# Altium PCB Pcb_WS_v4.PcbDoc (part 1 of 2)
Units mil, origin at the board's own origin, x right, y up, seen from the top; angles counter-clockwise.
Board outline 3890 x 3890 mil, 2 copper layers (Top Layer, Bottom Layer); 77 components, 63 nets, 250 pads, 399 vias.
Unrouted connection lines stored in the file: 3.
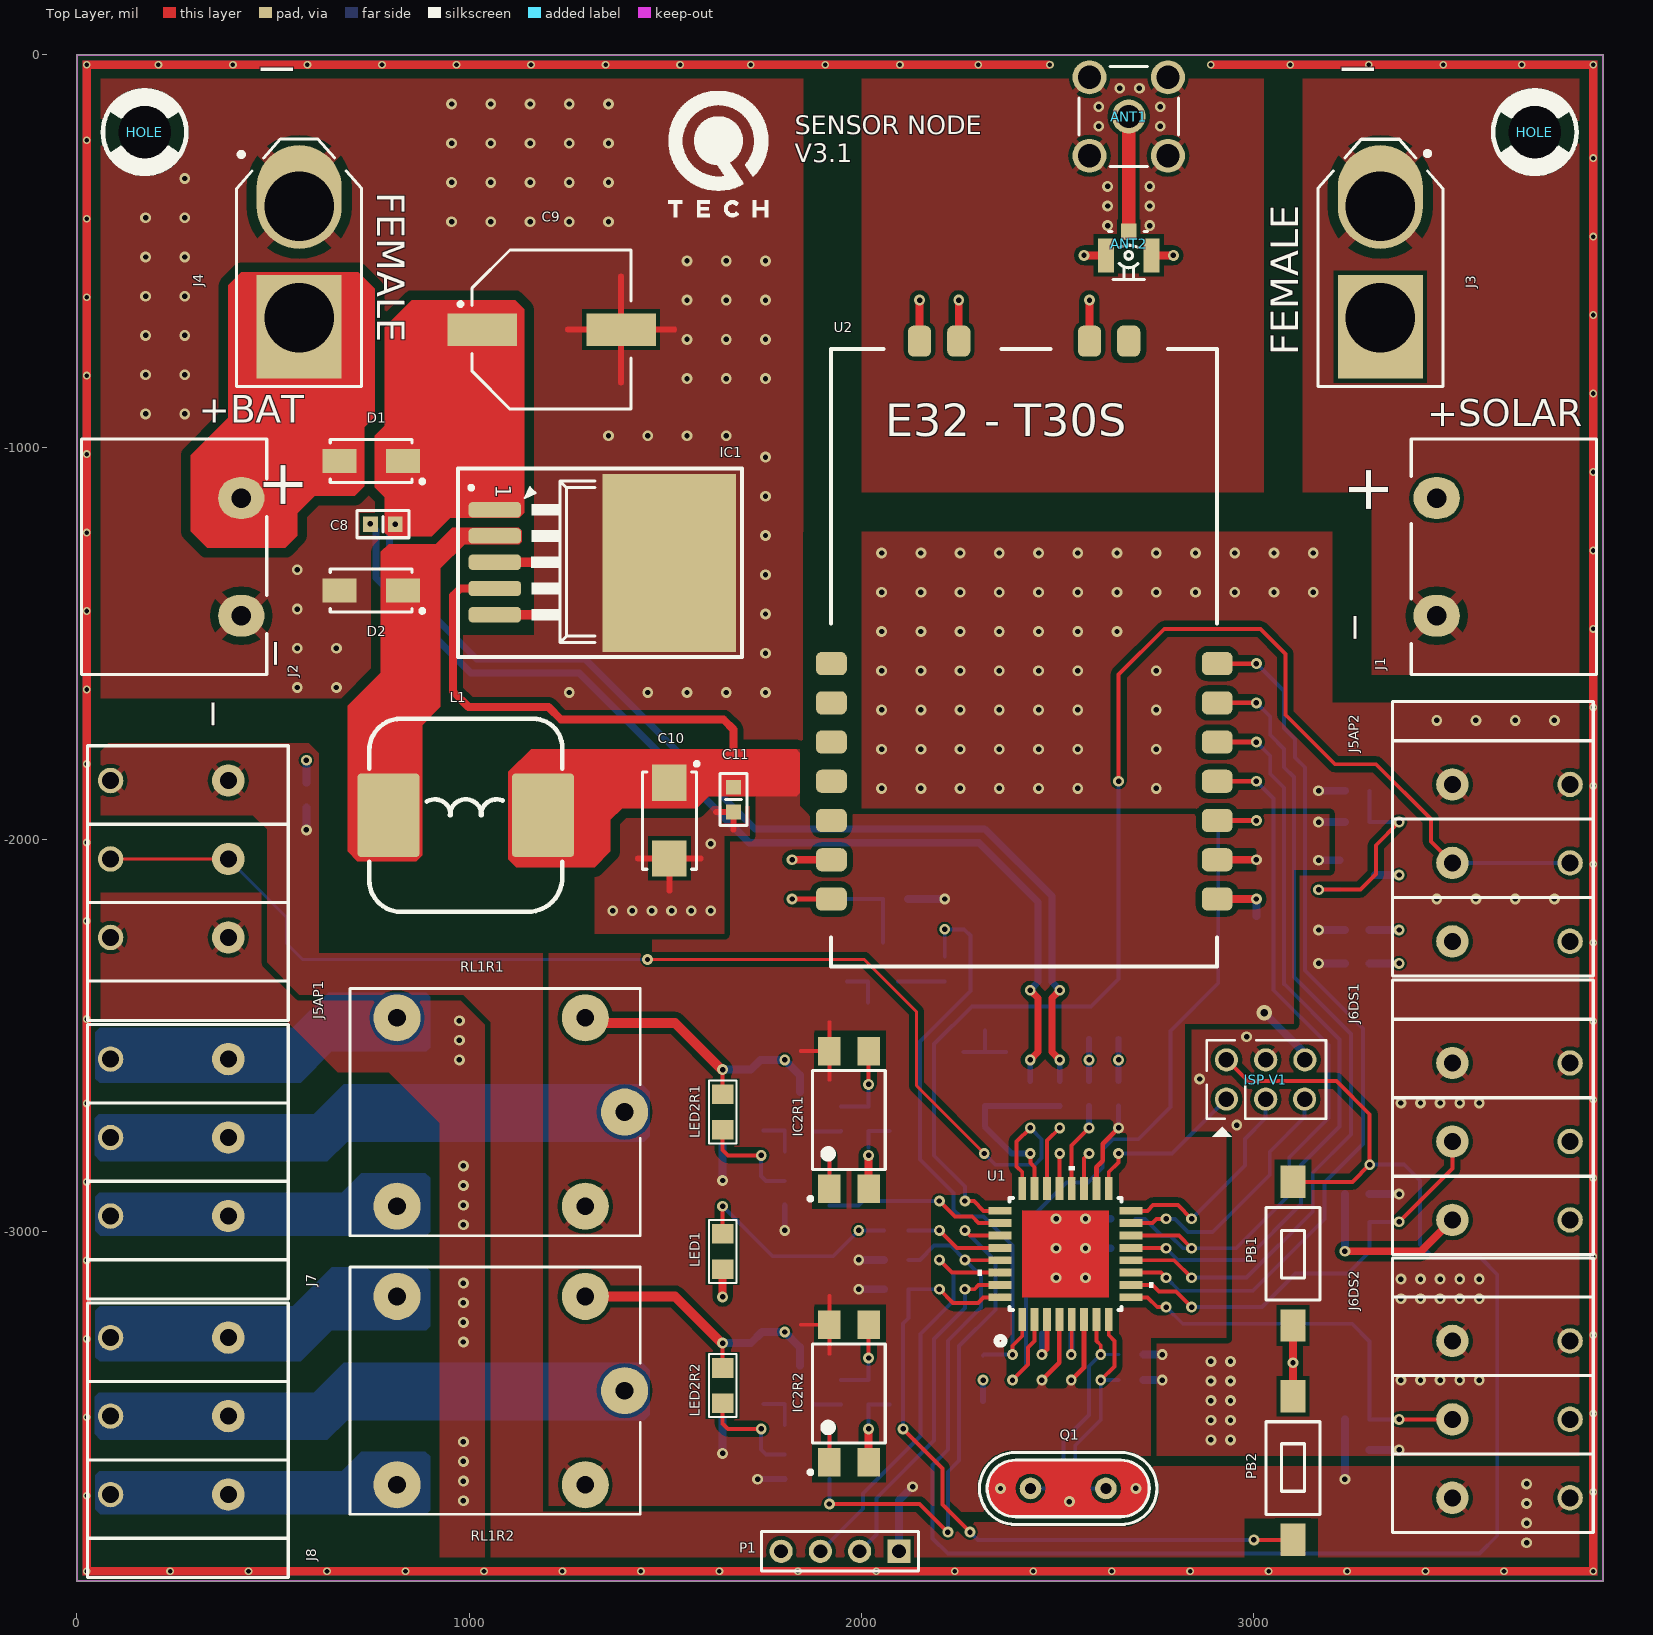
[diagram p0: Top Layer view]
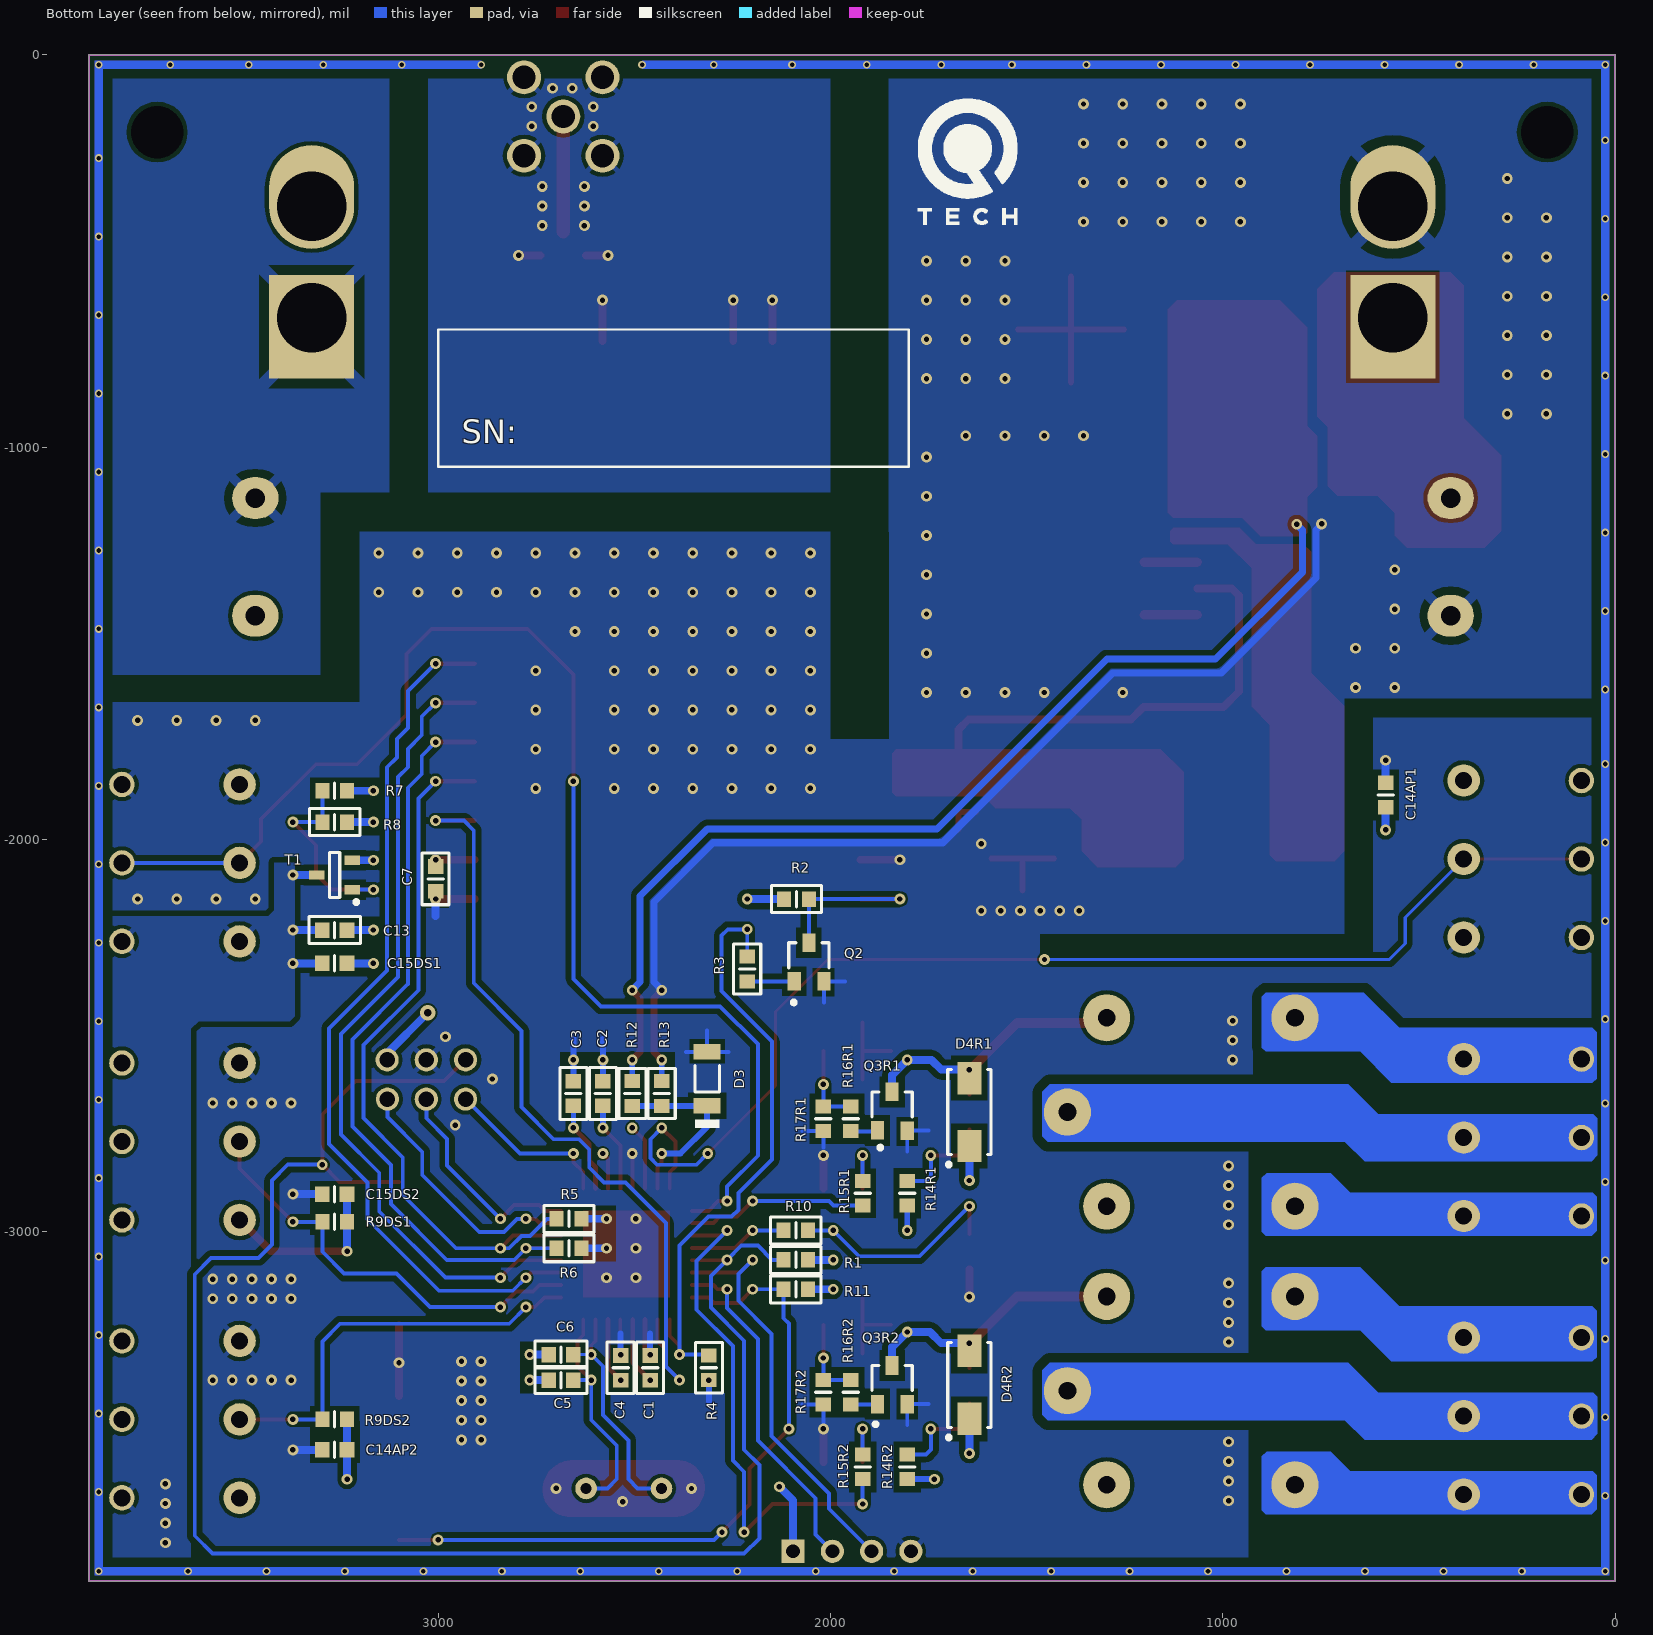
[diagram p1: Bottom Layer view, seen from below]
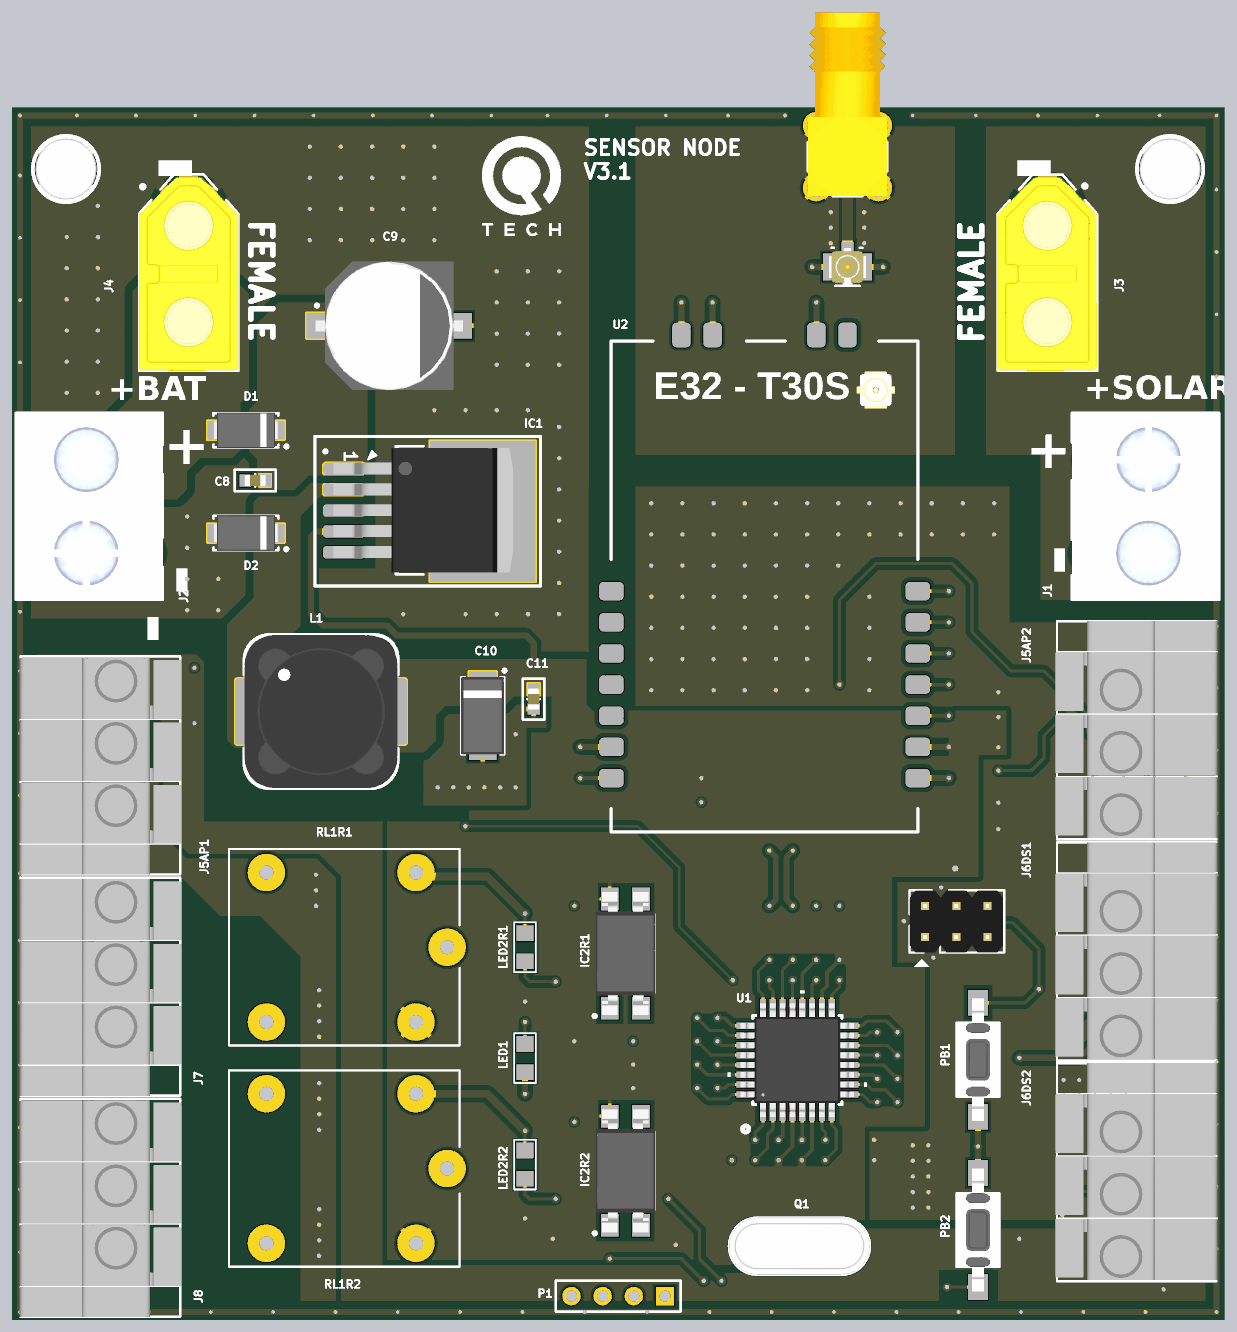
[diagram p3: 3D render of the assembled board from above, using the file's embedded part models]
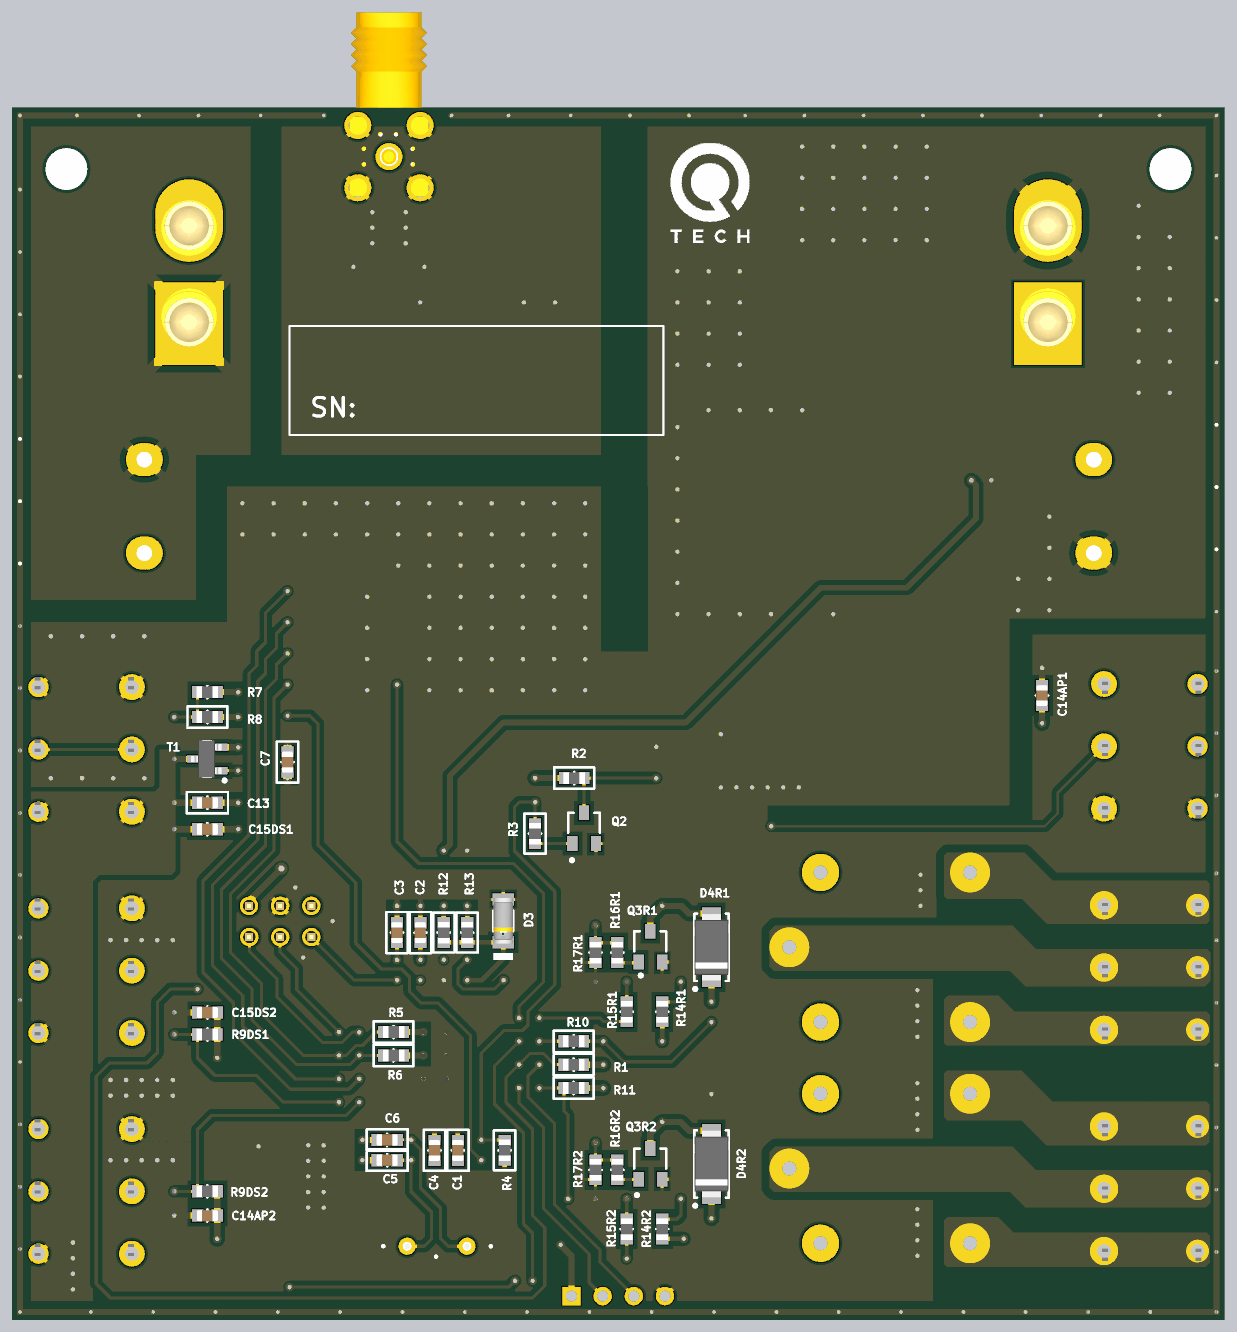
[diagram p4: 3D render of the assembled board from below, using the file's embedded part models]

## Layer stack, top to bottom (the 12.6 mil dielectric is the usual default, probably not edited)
Top Solder: solder mask 0.4, Solder Resist, Dk 3.5
Top Layer: signal copper 1.4
Dielectric 1: dielectric 12.6, FR-4, Dk 4.8
Bottom Layer: signal copper 1.4
Bottom Solder: solder mask 0.4, Solder Resist, Dk 3.5

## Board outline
0,-3890 0,0 3890,0 3890,-3890

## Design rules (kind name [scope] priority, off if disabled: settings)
Clearance ANT [InNet('ANT_M1') vs InNet('GND_ANT')] p1: gap=10 ignorepadtopadclearanceinfootprint=FALSE
Clearance Keep_Out [OnLayer('Keep-Out Layer')] p2: gap=5 ignorepadtopadclearanceinfootprint=FALSE
Clearance [All] p3: gap=10 ignorepadtopadclearanceinfootprint=FALSE except(5: Via-Poly Via-Region; 15: Track-Poly Track-Region SMDPad-Poly SMDPad-Region Poly-Poly; 25: Poly-Region)
ComponentClearance KF-conn_Clearance [InComponentClass('KF_conn') vs InComponentClass('KF_conn')] p1: gap=5 collisioncheckmode=3 verticalgap=0 showdistances=FALSE
ComponentClearance HS_Comp_Clearance [InComponentClass('HS_Comp') vs IsComponent] p2: gap=165 collisioncheckmode=3 verticalgap=0 showdistances=FALSE
ComponentClearance IC_Comp_Clearance [InComponentClass('IC_Comp') vs IsComponent] p3: gap=150 collisioncheckmode=3 verticalgap=0 showdistances=FALSE
ComponentClearance conn-th_Clearance [InComponentClass('conn-th') vs IsComponent and not InComponentClass('conn-th')] p4: gap=150 collisioncheckmode=3 verticalgap=0 showdistances=FALSE
ComponentClearance chip-ge_Clearance [InComponentClass('chip-ge') vs InAnyComponent] p5: gap=75 collisioncheckmode=3 verticalgap=0 showdistances=FALSE
ComponentClearance chip-0603_Clearance [InComponentClass('chip-0603') vs IsComponent] p6: gap=25 collisioncheckmode=3 verticalgap=0 showdistances=FALSE
HoleSize [All] p1: absolutevalues=TRUE maxlimit=100 minlimit=11.81 maxpercent=80.000 minpercent=20.000
HoleToHoleClearance [All] p1: gap=20 allowstackedmicrovias=TRUE
MinimumSolderMaskSliver MinimumForIC [HasFootprint('32A_ATM-M') vs HasFootprint('32A_ATM-M')] p1: minsoldermaskwidth=3
MinimumSolderMaskSliver [All] p2: minsoldermaskwidth=5
NetAntennae [All] p1 off: netantennaetolerance=0
PolygonConnect [All] p1: thpad.connectstyle=Relief thpad.reliefconductorwidth=13.78 thpad.reliefentries=4 thpad.polygonreliefangle="45 Angle" thpad.airgapwidth=10 smdpad.connectstyle=NoConnect smdpad.reliefconductorwidth=11.81 smdpad.reliefentries=4 smdpad.polygonreliefangle="45 Angle" smdpad.airgapwidth=10 via.connectstyle=Direct via.reliefconductorwidth=10 via.reliefentries=4 via.polygonreliefangle="90 Angle" via.airgapwidth=10
RoutingVias [All] p1: holewidth=13.78 width=27.56 viastyle="Through Hole" minholewidth=11.81 minwidth=23.62 maxholewidth=19.68 maxwidth=39.37
SilkToSilkClearance [All] p1: silktosilkclearance=3
SilkToSolderMaskClearance [IsPad] p1: minsilkscreentomaskgap=5 clearancetoexposedcopper=TRUE
SolderMaskExpansion [All] p1: expansion=4 istentingtop=FALSE
Width [All] p1: maxlimit=196.85 minlimit=8 preferedwidth=10
23 further rules are at their usual default settings.

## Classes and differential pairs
polygon class "New Class": AutoNaming "Top Layer-No Net"
component class KF_conn: J5AP1 J5AP2 J6DS1 J6DS2 J7 J8
component class HS_Comp: ANT1 ANT2 Q1
component class IC_Comp: IC1 IC2R1 IC2R2 L1 U1 U2
component class chip-ge: C9 C10 D1 D2 D4R1 D4R2
component class conn-th: "ISP V1" J1 J2 J3 J4 J5AP1 J5AP2 J6DS1 J6DS2 J7 J8 P1 PB1 PB2 RL1R1 RL1R2
component class chip-0603: C1 C2 C3 C4 C5 C6 C7 C8 C11 C13 C14AP1 C14AP2 C15DS1 C15DS2 D3 LED1 LED2R1 LED2R2 Q2 Q3R1 Q3R2 R1 R2 R3 R4 R5 R6 R7 R8 R9DS1 R9DS2 R10 R11 R12 R13 R14R1 R14R2 R15R1 R15R2 R16R1 R16R2 R17R1 R17R2 T1
channel class Sensor_DS18b20_1Wire: DS1 DS2
channel class Sensor_AirPressure_1Wire: AP1 AP2
channel class Relay: R1 R2
component class Top_Level: D3 HOLE J7 J8 LED1 P1 PB2 R10 R11 R12 R13
component class R2: D4R2 IC2R2 LED2R2 Q3R2 R14R2 R15R2 R16R2 R17R2 RL1R2
component class R1: D4R1 IC2R1 LED2R1 Q3R1 R14R1 R15R1 R16R1 R17R1 RL1R1
component class Main: C1 C2 C3 C4 C5 C6 "ISP V1" PB1 Q1 R1 U1
component class Lora: ANT1 ANT2 C7 Q2 R2 R3 R4 R5 R6 U2
component class DS2: C15DS2 J6DS2 R9DS2
component class DS1: C15DS1 J6DS1 R9DS1
component class AP2: C14AP2 J5AP2
component class AP1: C14AP1 J5AP1
component class PWR: C8 C9 C10 C11 C13 D1 D2 IC1 J1 J2 J3 J4 L1 R7 R8 T1

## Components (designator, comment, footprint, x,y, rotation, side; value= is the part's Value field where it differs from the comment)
ANT1 "Coax_1Female_1Shield" "HUBER-SUHNER_85 SMA-50-0-101/111 NE" 2680.84,-157 r90 top
ANT2 "U.FL" HIROSE_U.FL-R-SMT-1(10) 2680.84,-511 r180 top
C1 "100nF" CAPC1608X87N 2459.61,-3346.32 r90 bottom
C2 "100nF" CAPC1608X87N 2580,-2647.18 r270 bottom
C3 "100nF" CAPC1608X87N 2655,-2647.18 r90 bottom
C4 "100nF" CAPC1608X87N 2534.61,-3346.32 r90 bottom
C5 "100nF" CAPC1608X87N 2686.8,-3377.82 r0 bottom value=22pF
C6 "100nF" CAPC1608X87N 2686.8,-3312.82 r0 bottom value=22pF
C7 "100nF" CAPC1608X87N 3006.43,-2100 r270 bottom
C8 "100nF" CAPC1608X87N 780,-1196.11 r180 top
C9 "470uF" CAPAE1030X1020N 1210,-700 r0 top
C10 "100uF" CAPMP6032X280N 1510,-1951.51 r270 top
C11 "100nF" CAPC1608X87N 1673.55,-1898 r270 top
C13 "100nF" CAPC1608X87N 3263.5,-2230.54 r180 bottom
C14AP1 "100nF" CAPC1608X87N 585,-1886.5 r270 bottom (schematic designator C14)
C14AP2 "100nF" CAPC1608X87N 3263.5,-3555.54 r180 bottom (schematic designator C14)
C15DS1 "100nF" CAPC1608X87N 3263.5,-2315.54 r0 bottom (schematic designator C15)
C15DS2 "100nF" CAPC1608X87N 3263.5,-2903.69 r180 bottom (schematic designator C15)
D1 "SS16" DIOM5127X229N 750,-1035 r180 top
D2 "SS16" DIOM5127X229N 750,-1365 r180 top
D3 "BZV55-B5V1" DIOMELF3515N 2314.07,-2609.78 r90 bottom
D4R1 "BZG03C220" DIOM5326X230N 1645.86,-2694.46 r90 bottom (schematic designator D4)
D4R2 "BZG03C220" DIOM5326X230N 1645.86,-3390 r90 bottom (schematic designator D4)
HOLE "HOLE" "HOLE M3" 3716.02,-196.86 r0 top
HOLE "HOLE" "HOLE M3" 172.71,-196.86 r0 top
IC1 "LM2596" TO263-5 1065.04,-1159.18 r270 top
IC2R1 "SFH6156-4" SOIC254P977X406-4N 1967.86,-2714.46 r90 top (schematic designator IC2)
IC2R2 "SFH6156-4" SOIC254P977X406-4N 1967.86,-3411.74 r90 top (schematic designator IC2)
"ISP V1" "Connector 3x2" JP3x2 3030,-2611.61 r0 top
J1 "CON KF7.62-2P" "CON KF7.62-2P" 3465.86,-1279.46 r270 top locked
J2 "CON KF7.62-2P" "CON KF7.62-2P" 418.93,-1279.46 r90 top locked
J3 "XT60-FM" XT60-FM 3322.31,-527.57 r270 top locked
J4 "XT60-FM" XT60-FM 566.41,-527.57 r270 top locked
J5AP1 "KF142V-3P" "CON KF142V-3P-5.08" 85.86,-1849.46 r270 top (schematic designator J5)
J5AP2 "KF142V-3P" "CON KF142V-3P-5.08" 3805.86,-2259.46 r90 top (schematic designator J5)
J6DS1 "KF142V-3P" "CON KF142V-3P-5.08" 3805.86,-2969.46 r90 top (schematic designator J6)
J6DS2 "KF142V-3P" "CON KF142V-3P-5.08" 3805.86,-3677.74 r90 top (schematic designator J6)
J7 "KF142V-3P" "CON KF142V-3P-5.08" 85.86,-2559.46 r270 top
J8 "KF142V-3P" "CON KF142V-3P-5.08" 85.86,-3269.46 r270 top
L1 "33uH" L_SMD 794.25,-1938 r90 top
LED1 "LED" L-0805 1645.86,-3050 r270 top value="LED 3 ly Single Colour"
LED2R1 "LED" L-0805 1645.86,-2694.46 r90 top value="LED 3 ly Single Colour" (schematic designator LED2)
LED2R2 "LED" L-0805 1645.86,-3391.74 r90 top value="LED 3 ly Single Colour" (schematic designator LED2)
P1 "Header 4" HDR1X4 2095,-3814 r180 top
PB1 "Push Button" PB_TYCO_FSMSM 3099.53,-3055.38 r270 top
PB2 "Push Button" PB_TYCO_FSMSM 3099.53,-3601.93 r90 top
Q1 "20MHz" XTAL_HC-49/U 2526.55,-3653.88 r0 top
Q2 "C1815" SOT23-3 2055.2,-2312.2 r180 bottom
Q3R1 "C1815" SOT23-3 1842.86,-2692.41 r180 bottom (schematic designator Q3)
Q3R2 "C1815" SOT23-3 1842.86,-3389.69 r180 bottom (schematic designator Q3)
R1 "10k" RESC1608X55N 2088.21,-3071.21 r0 bottom
R2 "10k" RESC1608X55N 2086.5,-2151.51 r0 bottom value=4k7
R3 "10k" RESC1608X55N 2212.06,-2329.71 r270 bottom value=1k
R4 "10k" RESC1608X55N 2309.61,-3346.32 r90 bottom value=1k
R5 "4k7" RESC1608X55N 2666.17,-2966.61 r180 bottom value=10k
R6 "4k7" RESC1608X55N 2666.17,-3041.61 r180 bottom value=10k
R7 "1k" RESC1608X55N 3263.5,-1875.54 r0 bottom
R8 "10k" RESC1608X55N 3263.5,-1955.54 r0 bottom
R9DS1 "4k7" RESC1608X55N 3263.5,-2974.23 r180 bottom (schematic designator R9)
R9DS2 "4k7" RESC1608X55N 3263.5,-3477.74 r180 bottom (schematic designator R9)
R10 "10k" RESC1608X55N 2088.21,-2996.21 r180 bottom value=200
R11 "10k" RESC1608X55N 2088.21,-3146.21 r0 bottom
R12 "10k" RESC1608X55N 2505,-2647.18 r270 bottom value=2M
R13 "10k" RESC1608X55N 2430,-2647.18 r90 bottom value=1M
R14R1 "1k" RESC1608X55N 1804.06,-2901.48 r90 bottom value=200 (schematic designator R14)
R14R2 "1k" RESC1608X55N 1804.06,-3598.76 r90 bottom value=200 (schematic designator R14)
R15R1 "1k" RESC1608X55N 1917.86,-2901.48 r90 bottom (schematic designator R15)
R15R2 "1k" RESC1608X55N 1917.86,-3598.76 r90 bottom (schematic designator R15)
R16R1 "1k" RESC1608X55N 1947.86,-2711.48 r270 bottom value=200 (schematic designator R16)
R16R2 "1k" RESC1608X55N 1947.86,-3408.76 r270 bottom value=200 (schematic designator R16)
R17R1 "10k" RESC1608X55N 2017.86,-2711.48 r90 bottom (schematic designator R17)
R17R2 "10k" RESC1608X55N 2017.86,-3408.76 r90 bottom (schematic designator R17)
RL1R1 "Relay 10A/12V" RL_SPDT_10A 1395.86,-2694.46 r180 top value="Relay SPDT, 10A, 12V" (schematic designator RL1)
RL1R2 "Relay 10A/12V" RL_SPDT_10A 1395.86,-3404.46 r180 top value="Relay SPDT, 10A, 12V" (schematic designator RL1)
T1 "BSH203" SOT95P230X110-3N 3263.5,-2090.26 r0 bottom
U1 "ATmega328-AU" 32A_ATM-M 2519.8,-3056.41 r90 top
U2 "E32-T30S" E32-T30S 2906.43,-749.15 r180 top

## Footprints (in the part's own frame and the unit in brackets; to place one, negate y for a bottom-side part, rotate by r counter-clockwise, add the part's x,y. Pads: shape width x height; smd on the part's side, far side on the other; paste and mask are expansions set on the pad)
32A_ATM-M [mil]
  rect 58x20 smd: 1(-167,110.24) 2(-167,78.74) 3(-167,47.24) 4(-167,15.75) 5(-167,-15.75) 6(-167,-47.24) 7(-167,-78.74) 8(-167,-110.24) 17(167,-110.24) 18(167,-78.74) 19(167,-47.24) 20(167,-15.75) 21(167,15.75) 22(167,47.24) 23(167,78.74) 24(167,110.24)
  rect 20x58 smd: 9(-110.24,-167) 10(-78.74,-167) 11(-47.24,-167) 12(-15.75,-167) 13(15.75,-167) 14(47.24,-167) 15(78.74,-167) 16(110.24,-167) 25(110.24,167) 26(78.74,167) 27(47.24,167) 28(15.75,167) 29(-15.75,167) 30(-47.24,167) 31(-78.74,167) 32(-110.24,167)
  silkscreen extent -231,-224 224,224, body extent -182,-182 182,182, height 47
CAPAE1030X1020N [mm] "Capacitor, Aluminium Electrolytric, 10.3mm L X 10.3mm W X 10.2mm H, IPC Medium Density"
  rect 4.5x2.1 smd: 1(-4.5,0) 2(4.5,0)
  silkscreen extent -6.02,-5.15 5.15,5.15, body extent -6,-5.25 6,5.25, height 10.2
CAPC1608X87N [mm] "Chip Capacitor, Body 1.6x0.8mm IPC Medium Density"
  rect 0.95x1 smd: 1(-0.8,0) 2(0.8,0)
  silkscreen extent -1.68,-0.87 1.68,0.87, body extent -0.87,-0.47 0.88,0.48, height 0.87
CAPMP6032X280N [mm] "Capacitor, Polarized, Molded  Body 6.0x3.2mm, IPC Medium Density"
  rect 2.35x2.25 smd: 1(-2.45,0) 2(2.45,0)
  silkscreen extent -3.8,-1.75 3.15,1.9, body extent -3.15,-1.75 3.15,1.75, height 2.8
"CON KF7.62-2P" [mm]
  oval 2.7x3 hole 1.26: 1(-3.81,0) 2(3.81,0)
  silkscreen extent -7.62,-1.65 7.62,10.35, body extent -7.62,-1.65 7.62,10.35, height 12.4
"CON KF142V-3P-5.08" [mm]
  round 2.1 hole 1.1: 1(0,7.62) 2(5.08,7.62) 3(10.16,7.62)
  round 1.65 hole 1.1: 1(0,0) 2(5.08,0) 3(10.16,0)
  silkscreen extent -2.25,-1.5 15.53,11.5, body extent -2.14,-1.57 15.54,11.63, height 14.23
DIOM5127X229N [mm] "DO-214-AC/SMA Molded Diode, 2-Leads, Body 5.1x2.7mm, IPC Medium Density"
  rect 2.2x1.55 smd: 1(-2.05,0) 2(2.05,0)
  silkscreen extent -3.43,-1.4 2.65,1.45, body extent -2.67,-1.45 2.68,1.45, height 2.29
DIOM5326X230N [mm] "DO-214-AC/SMA Molded Diode, Body 5.3x2.6mm, IPC Medium Density"
  rect 2.1x1.55 smd: 1(-2.2,0) 2(2.2,0)
  silkscreen extent -3.52,-1.4 2.75,1.45, body extent -2.75,-1.4 2.75,1.4, height 2.3
DIOMELF3515N [mm] "SOD80C, MELF Diode, 2-Leads, Body 3.5x1.5mm, IPC Medium Density"
  rect 1x1.75 smd: 1(-1.75,0) 2(1.75,0)
  silkscreen extent -3.18,-0.8 0.85,0.8, body extent -1.85,-0.8 1.85,0.8, height 1.6
E32-T30S [mm] "Lora-EBYTE-21~30dBm-UART-SX1278-25x40mm"
  rrect50% 2x1.5 smd: 1(0,20.38) 2(0,22.92) 3(0,25.46) 4(0,28) 5(0,30.54) 6(0,33.08) 7(0,35.62) 8(24.98,35.62) 9(24.98,33.08) 10(24.98,30.54) 11(24.98,28) 12(24.98,25.46) 13(24.98,22.92) 14(24.98,20.38)
  rrect50% 1.5x2 smd: 15(19.27,-0.5) 16(16.73,-0.5) 17(8.27,-0.5) 18(5.73,-0.5)
  silkscreen extent 0,0 25,40, body extent 0,0 25,40, height 3.5
HDR1X4 [mm] "Connector; Header; 4 Position"
  rect 1.5x1.5 hole 0.9: 1(0,0)
  round 1.5 hole 0.9: 2(2.54,0) 3(5.08,0) 4(7.62,0)
  silkscreen extent -1.27,-1.27 8.89,1.27
HIROSE_U.FL-R-SMT-1(10) [mm] "Up to 6GHz Ultra Small Surface Mount Male Coaxial Connectors U.FL Series"
  rect 1x1.05 smd: 1(0,-1.525)
  rect 1.05x2.2 smd: 2(-1.475,0) 2(1.475,0)
  silkscreen extent -1.21,-1.55 1.3,1.55, body extent -1.5,-1.55 1.5,1.55, height 1.25
"HOLE M3" [mm]
  round 3.2 hole 3.4 unplated mask+0.1: 1(0,0)
  Top Layer pour cut-out: -2.846,0.006 -2.628,1.101 -2.007,2.029 -1.077,2.646 0.019,2.859 0.019,2.859 1.117,2.635 2.042,2.003 2.649,1.062 2.845,-0.041 2.845,-0.041 2.628,-1.12 2.013,-2.033 1.094,-2.64 0.012,-2.845 0.012,-2.845 -1.086,-2.638 -2.017,-2.021 -2.636,-1.091 -2.846,0.006
  silkscreen extent -2.7,-2.7 2.7,2.7, body extent -2.5,-2.5 2.5,2.5, height 1.73
"HUBER-SUHNER_85 SMA-50-0-101/111 NE" [mm] "50 Ohm SMA Right Angle PCB Jack"
  round 2.2 hole 1.5: 1(0,0) 2(-2.54,-2.54) 2(-2.54,2.54) 2(2.54,-2.54) 2(2.54,2.54)
  silkscreen extent -3.23,-3.23 3.23,3.23, body extent -3.23,-3.23 11.73,3.23, height 9.6
JP3x2 [mm] "Connector 3x2"
  round 1.5 hole 1: 1(-2.54,-1.27) 2(0,-1.27) 3(2.515,-1.27) 4(-2.54,1.27) 5(0,1.27) 6(2.54,1.27)
  silkscreen extent -3.81,-3.71 3.91,2.54, body extent -3.81,-2.54 3.81,2.54, height 8.52
L-0805 [mil] "Compoment SMD 80x50mil"
  rect 50x55 smd: 1(-45,0) 2(45,0)
  silkscreen extent -80,-35 80,35, body extent -50,-20 50,20, height 43
L_SMD [mm]
  rrect10% 5.4x4 smd mask+0.1: 1(0,0) 2(0,-10)
  silkscreen extent -6.25,-11.25 6.25,1.25, body extent -6.25,-11.25 6.25,1.25, height 6.7
PB_TYCO_FSMSM [mm] "Body 3.5x6.0mm, Pushbutton Switch,  TYCO FSMSM Serie"
  rect 2.1x1.6 smd: 1(-4.65,0) 2(4.65,0)
  silkscreen extent -3,-1.75 3,1.75, body extent -5,-1.75 5,1.75, height 4.3
RESC1608X55N [mm] "Chip Resistor, EIA 0603, Metric 1608, Body 1.6x0.8mm, IPC Medium Density"
  rect 0.9x1 smd: 1(-0.8,0) 2(0.8,0)
  silkscreen extent -1.63,-0.87 1.63,0.87, body extent -0.87,-0.47 0.88,0.48, height 0.55
RL_SPDT_10A [mil] "Relay SPDT, 5 pin, 10A,W 650mil, L 800mil, H 800mil"
  round 120 hole 45: 1(0,0) 2(580,240) 3(580,-240) 4(100,-240) 5(100,240)
  silkscreen extent -40,-315 700,315
SOIC254P977X406-4N [mm] "SOIC, 2.54mm pitch; 4 pin, 6.65mm W X 4.69mm L, IPC Medium Density"
  rect 1.85x1.45 smd: 1(-4.45,1.27) 2(-4.45,-1.27) 3(4.45,-1.27) 4(4.45,1.27)
  silkscreen extent -5.22,-2.35 3.2,2.62, body extent -5.01,-2.41 5.02,2.42, height 4.06
SOT23-3 [mm] "SOT 23"
  rect 0.85x1.2 smd: 1(-0.94,-1.245) 2(0.985,-1.25) 3(0.005,1.25)
  silkscreen extent -1.29,-2.74 1.31,1.25, body extent -1.5,-1.5 1.52,1.5, height 1.27
SOT95P230X110-3N [mm] "SOT23, 3 pin, Pitch 0.95mm - 1.3mm W X 2.9mm L X 1.1mm H, IPC Medium Density"
  rect 1x0.6 smd: 1(-1.15,0.95) 2(-1.15,-0.95) 3(1.15,0)
  silkscreen extent -1.52,-1.45 0.33,1.87, body extent -1.17,-1.5 1.33,1.5, height 1.1
TO263-5 [mm]
  rrect50% 1x3.4 smd: 1(0,0) 2(1.7,0) 4(5.1,0) 5(6.8,0)
  rrect50% 1x3.4 smd mask+0: 3(3.4,0)
  rect 11.5x8.634 smd: 6(3.45,11.302)
  silkscreen extent -2.66,-2.38 9.54,16.02, body extent -1.71,-0.87 8.45,13.77, height 4.57
XT60-FM [mm]
  oval 6.716x5.516 hole 4.5 copper offset -0.6,0: 1(-3.6,0)
  rect 6.716x5.516 hole 4.5 copper offset 0.6,0: 2(3.6,0)
  silkscreen extent -7.94,-4.05 8.06,4.05, body extent -7.81,-4.07 8.12,4.06, height 15.5
XTAL_HC-49/U [mm] "HC-49/U Leaded Cristal, Body 11.05x4.8mm; Pitch 4.88mm"
  round 1.4 hole 0.7: 1(-2.44,0) 2(2.44,0)
  silkscreen extent -5.75,-2.33 5.75,2.33, body extent -5.75,-2.33 5.75,2.33, height 3.5

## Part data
ANT1: library part HUBER-SUHNER_85_SMA-50-0-101/111_NE, Manufacturer=HUBER+SUHNER, Manufacturer Part Number=85_SMA-50-0-101/111_NE
ANT2: library part HIROSE_U.FL-R-SMT-1(10), Manufacturer="HIROSE (HRS)", Manufacturer Part Number=U.FL-R-SMT-1(10)
C1 C2 C3 C4 C7 C8 C11 C13 C14AP1 C14AP2 C15DS1 C15DS2: library part CC0603_100NF_50V_10%_X7R, "Non-polarised capacitor", Case=0603, Manufacturer=GENERIC, Manufacturer1 ComponentHeight=0.87mm, Manufacturer1 Example=PHYCOMP, Manufacturer1 Part Number=223858615649, Tolerance=±10%, Voltage=50V
C5 C6: library part CC0603_22PF_50V_5%_NP0, "Non-polarised capacitor", Case=0603, Manufacturer=GENERIC, Manufacturer1 ComponentHeight=0.87mm, Manufacturer1 Example=PHYCOMP, Manufacturer1 Part Number=223886715229, Tolerance=±5%, Voltage=50V
C9: library part CAE1030-1020_470UF_25V_20%, "Polarised capacitor", Case=G, Manufacturer=GENERIC, Manufacturer1 ComponentHeight=10.2mm, Manufacturer1 Example=PANASONIC, Manufacturer1 Part Number=EEEFK1E471AP, Tolerance=±20%, Voltage=25V
C10: library part CTE6032-28_100UF_6.3V_10%_LESR0075, "Polarised capacitor", Case=C, Manufacturer=GENERIC, Manufacturer1 ComponentHeight=2.8mm, Manufacturer1 Example=AVX, Manufacturer1 Part Number=TPSC107K006R0075, Tolerance=±10%, Voltage=6.3V
D1 D2: "Schottky Diode", Case=DO-214AC, Manufacturer="VISHAY GENERAL SEMICONDUCTOR", Power=1A, Voltage=60V
D3: "Zener Diode", Case=SOD-80C, Manufacturer="NXP SEMICONDUCTORS", Power=500mW, Voltage=5V1
D4R1 D4R2: "Zener Diode", Case=DO-214AC, Manufacturer="VISHAY SEMICONDUCTOR", Power=1.25W, Voltage=220V
HOLE HOLE: library part "HOLE M3"
IC1: library part LM2596-5V
IC2R1 IC2R2: "Single Optocoupler", Case=SOIC4, Manufacturer="VISHAY SEMICONDUCTORS"
"ISP V1": library part JP3x2
J3 J4: Package="Package Analog Devices"
J5AP1 J5AP2 J6DS1 J6DS2 J7 J8: library part "CON KF142V-3P-5.08", "CON KF142V-3P-5.08"
L1: library part "L_SMD 33uH"
LED1 LED2R1 LED2R2: "LED Single colour Green and Red"
P1: "Header, 4-Pin"
PB1 PB2: "Push-Button Switch SPDT", Manufacturer="TYCO ELECTRONICS", Manufacturer Part Number="FSMSM or 1437566-3", Part Number=PB_TYCO_FSMSM
Q1: library part XTAL_20MHZ_AEL_HC-49/U, "Quartz Crystal", Manufacturer="AEL CRYSTALS", Manufacturer Part Number=X20M000000L010
Q2 Q3R1 Q3R2: library part 2SC1815, PSpiceTemplate="Q^@REFDES %c %b %e @MODEL"
R1 R5 R6 R8 R11 R17R1 R17R2: library part R0603_10K_1%_0.1W_100PPM, "Resistor - 1%", Case=0603, Manufacturer=GENERIC, Manufacturer1 ComponentHeight=0.55mm, Manufacturer1 Example="NIC COMPONENT", Manufacturer1 Part Number=NRC06F1002TRF, Power=0.1W, Tolerance=±1%
R2 R9DS1 R9DS2: library part R0603_4K7_1%_0.1W_100PPM, "Resistor - 1%", Case=0603, Manufacturer=GENERIC, Manufacturer1 ComponentHeight=0.55mm, Manufacturer1 Example="NIC COMPONENT", Manufacturer1 Part Number=NRC06F4701TRF, Power=0.1W, Tolerance=±1%
R3 R4 R7 R15R1 R15R2: library part R0603_1K_1%_0.1W_100PPM, "Resistor - 1%", Case=0603, Manufacturer=GENERIC, Manufacturer1 ComponentHeight=0.55mm, Manufacturer1 Example="NIC COMPONENT", Manufacturer1 Part Number=NRC06F1001TRF, Power=0.1W, Tolerance=±1%
R10 R14R1 R14R2 R16R1 R16R2: library part R0603_200R_1%_0.1W_100PPM, "Resistor - 1%", Case=0603, Manufacturer=GENERIC, Manufacturer1 ComponentHeight=0.55mm, Manufacturer1 Example="NIC COMPONENT", Manufacturer1 Part Number=NRC06F2000TRF, Power=0.1W, Tolerance=±1%
R12: library part R0603_2M_1%_0.1W_100PPM, "Resistor - 1%", Case=0603, Manufacturer=GENERIC, Manufacturer1 ComponentHeight=0.55mm, Manufacturer1 Example="NIC COMPONENT", Manufacturer1 Part Number=NRC06F2004TRF, Power=0.1W, Tolerance=±1%
R13: library part R0603_1M_1%_0.1W_100PPM, "Resistor - 1%", Case=0603, Manufacturer=GENERIC, Manufacturer1 ComponentHeight=0.55mm, Manufacturer1 Example="NIC COMPONENT", Manufacturer1 Part Number=NRC06F1004TRF, Power=0.1W, Tolerance=±1%
RL1R1 RL1R2: library part "Relay 1", "Relay SPDT,10A - 12VDC 5 Pin"
T1: "P-CHANNEL MOSFET WITH DIODE", Case=SOT23-3, Manufacturer="NXP SEMICONDUCTORS"
U1: "8-bit AVR Microcontroller, 32KB Flash, 1KB EEPROM, 2KB SRAM, 32-pin TQFP, Industrial Grade (-40°C to 85°C)", Supplier Part Number 1=ATMEGA328-AU-ND
U2: library part E32-433T30S, "Lora Ebyte E32-T30S Module"

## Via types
v1: diameter 27.56, hole 13.78, Top Layer to Bottom Layer, tented both sides, 320 vias
v2: diameter 20, hole 11.81, Top Layer to Bottom Layer, tented both sides, 76 vias
v3: diameter 27.56, hole 13.78, Top Layer to Bottom Layer, tented top, 2 vias
v4: diameter 39.37, hole 19.68, Top Layer to Bottom Layer, tented both sides, 1 vias

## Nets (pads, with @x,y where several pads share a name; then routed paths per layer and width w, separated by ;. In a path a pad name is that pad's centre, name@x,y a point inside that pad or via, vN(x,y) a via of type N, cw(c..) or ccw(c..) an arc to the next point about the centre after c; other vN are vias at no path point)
ANT_M: U2.18
ANT_M1: ANT1.1 ANT2.1 | length 294
  Top Layer w34: ANT2.1@2680.84,-450.96 ANT1.1@2680.84,-157
AREF: C2.2 U1.20 | length 229.1
  Top Layer w10: U1.20@2535.55,-2889.41 2535.55,-2779.45 v1(2580,-2735)
  Bottom Layer w15: v1(2580,-2735) C2.2@2580,-2678.68
AUX: U1.2 U2.5 | length 2073.6
  Top Layer w10: v1(2384.61,-3377.82) 2424.61,-3337.82 2424.61,-3294.19 2441.06,-3277.74 U1.2@2441.06,-3223.41
  Top Layer w12: U2.5@2906.43,-1951.51 v1(3006.43,-1951.51)
  Bottom Layer w10: v1(2384.61,-3377.82) 2419,-3343.42 2419,-2977.3 2522.75,-2873.56 2577.2,-2873.56 2614.73,-2836.03 2614.73,-2790.06 2641.01,-2763.78 2705.43,-2763.78 2787.28,-2681.93 2787.28,-2487.72 2909,-2366 2909,-1976.7 2934.19,-1951.51 v1(3006.43,-1951.51)
BAT-VSEN: C8.1 C9.1 D1.1 IC1.1 R12.1 | length 2654.9
  Top Layer w18: v1(2505,-2561.61) 2485,-2541.61 2485,-2512.31 2485,-2404 v1(2505,-2384)
  Bottom Layer w15: R12.1@2505,-2615.69 v1(2505,-2561.61)
  Bottom Layer w18: v1(811.5,-1196.11) 811.5,-1196.94 797,-1211.43 797,-1318.76 1018.24,-1540 1295,-1540 1728,-1973 2313.83,-1973 2485,-2144.17 2485,-2363.3 2505,-2383.3 v1(2505,-2384)
BAT-VSEN-Q: D3.1 R12.2 R13.1 U1.23 | length 482.1
  Top Layer w10: v1(2430,-2800) 2430,-2824.02 2441.06,-2835.08 U1.23@2441.06,-2889.41
  Bottom Layer w15: v1(2430,-2800) 2382.4,-2800 2314.07,-2731.68 D3.1@2314.07,-2678.68 R13.1@2430,-2678.68 R12.2@2505,-2678.68
CLOSE1: J7.3 RL1R1.2
CLOSE2: J8.3 RL1R2.2
COM1: J7.2 RL1R1.1
COM2: J8.2 RL1R2.1
DATA-AP1: J5AP1.2 U1.24 | length 3115.9
  Top Layer w8: J5AP1.2@85.86,-2049.46 J5AP1.2@385.86,-2049.46 ; v1(1454.34,-2305.63) 2007.1,-2305.63 2140,-2438.52 2140,-2627.15 v1(2312.85,-2800)
  Top Layer w10: U1.24@2409.57,-2889.41 2409.57,-2847.57 2395,-2833 2395,-2770 v1(2430,-2735)
  Bottom Layer w8: J5AP1.2@385.86,-2049.46 535,-2198.6 535,-2265 575.63,-2305.63 v1(1454.34,-2305.63)
  Bottom Layer w10: v1(2312.85,-2800) 2341.63,-2828.78 2441.92,-2828.78 2458.78,-2811.92 2458.78,-2763.78 v1(2430,-2735)
DATA-AP2: J5AP2.2 U1.25 | length 3416.9
  Top Layer w10: v1(2263.39,-2921.21) 2286,-2921.21 2310.96,-2946.17 U1.25@2352.8,-2946.17 ; v1(2655,-1851.51) 2655,-1579.45 2771.45,-1463 3016.45,-1463 3080,-1526.55 3080,-1681.79 3206.21,-1808 3311.19,-1808 3451.23,-1948.04 3451.23,-2004.83 J5AP2.2@3505.86,-2059.46
  Bottom Layer w10: v1(2263.39,-2921.21) 2263.39,-2884.18 2185,-2805.79 2185,-2521.49 2281.49,-2425 2585.15,-2425 2655,-2355.15 v1(2655,-1851.51) ; J5AP2.2@3505.86,-2059.46 J5AP2.2@3805.86,-2059.46
DATA-DS1: J6DS1.2 R9DS1.1 U1.10 | length 1102.4
  Top Layer w10: U1.10@2686.8,-3135.15 2741.13,-3135.15 2757.59,-3151.61 2801.21,-3151.61 v1(2841.21,-3191.61) ; v1(3370,-2974.23) 3505.86,-2838.37 J6DS1.2@3505.86,-2769.46
  Bottom Layer w10: v1(2841.21,-3191.61) 3020.39,-3191.61 3105.7,-3106.29 3239.32,-3106.29 3295,-3050.61 R9DS1.1@3295,-2974.23 v1(3370,-2974.23)
DATA-DS2: J6DS2.2 R9DS2.1 U1.9 | length 1064.1
  Top Layer w10: U1.9@2686.8,-3166.65 2728.65,-3166.65 2753.61,-3191.61 v1(2776.21,-3191.61) ; v1(3370,-3477.74) J6DS2.2@3505.86,-3477.74
  Bottom Layer w10: v1(2776.21,-3191.61) 2818.61,-3234 3249.65,-3234 3295,-3279.35 R9DS2.1@3295,-3477.74 v1(3370,-3477.74)
EARTH: 
  other v2: 25,-3865 237.5,-3865 437.5,-3865 637.5,-3865 837.5,-3865 1037.5,-3865 1237.5,-3865 1437.5,-3865 1637.5,-3865 1837.5,-3865 2037.5,-3865 2237.5,-3865 2437.5,-3865 2637.5,-3865 2837.5,-3865 3037.5,-3865 3237.5,-3865 3437.5,-3865 3637.5,-3865 3865,-3865 25,-3672.5 3865,-3663 25,-3472.5 3865,-3463 25,-3272.5 3865,-3263 25,-3072.5 3865,-3063 25,-2872.5 3865,-2863 25,-2672.5 3865,-2663 3865,-2463 25,-2457.5 3865,-2263 25,-2207.5 3865,-2063 25,-2007.5 3865,-1863 25,-1807.5 3865,-1663 25,-1617.5 3865,-1463 25,-1417.5 3865,-1263 25,-1217.5 3865,-1063 25,-1017.5 3865,-863 25,-817.5 3865,-663 25,-617.5 3865,-463 25,-417.5 3865,-263 25,-217.5 25,-25 207.5,-25 397.5,-25 587.5,-25 777.5,-25 967.5,-25 1157.5,-25 1347.5,-25 1537.5,-25 1717.5,-25 1907.5,-25 2097.5,-25 2297.5,-25 2480,-25 2890,-25 3092.5,-25 3292.5,-25 3482.5,-25 3682.5,-25 3865,-25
